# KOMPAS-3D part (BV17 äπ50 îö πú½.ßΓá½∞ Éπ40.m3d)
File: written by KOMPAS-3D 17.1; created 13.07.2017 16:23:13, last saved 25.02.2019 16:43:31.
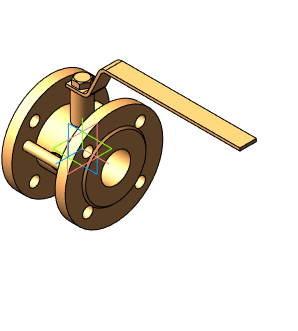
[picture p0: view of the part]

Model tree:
1. Операция без истории:3  (labels: Сталь 20  ГОСТ 1050-88)

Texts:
  DISO1
  DISO2
  BV17 Ду10 ФФ Ру40 угл. сталь
  BV17 Ду15 ФФ Ру40 угл. сталь
  BV17 Ду20 ФФ Ру40 угл. сталь
  BV17 Ду25 ФФ Ру40 угл. сталь
  BV17 Ду32 ФФ Ру40 угл. сталь
  BV17 Ду40 ФФ Ру40 угл. сталь
  BV17 Ду50 ФФ Ру40 угл. сталь
  BV17 Ду65 ФФ Ру40 угл. сталь
  BV17 Ду80 ФФ Ру40 угл. сталь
